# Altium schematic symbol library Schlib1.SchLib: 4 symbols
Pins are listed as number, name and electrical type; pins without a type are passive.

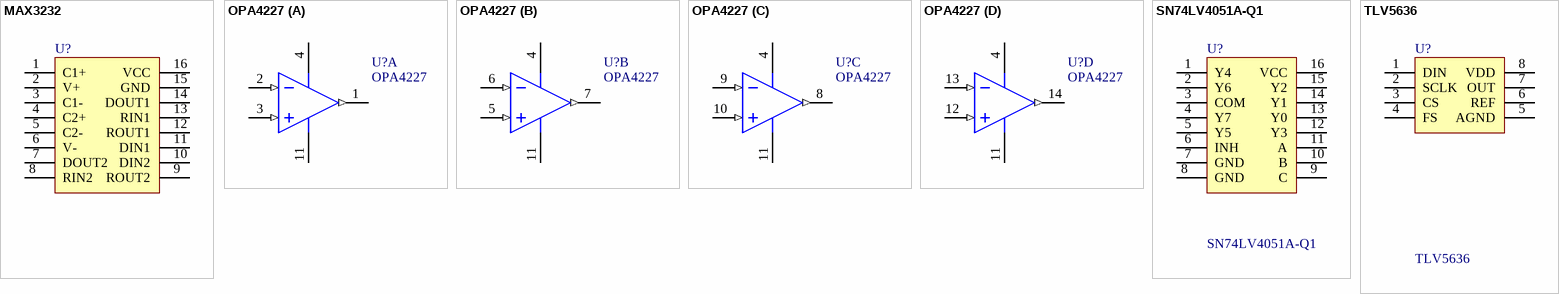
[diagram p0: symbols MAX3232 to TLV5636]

## MAX3232
designator U?
footprint MAX3232
footprint D014_L (SOIC, 14-Leads, Body 8.7x3.9mm, Pitch 1.27mm, IPC High Density)
footprint D014_M (SOIC, 14-Leads, Body 8.7x3.9mm, Pitch 1.27mm, IPC Low Density)
3D model D014 (14-Pin Small Outline Integrated Circuit 1.27 mm Pitch)
pins: 1 C1+, 2 V+, 3 C1-, 4 C2+, 5 C2-, 6 V-, 7 DOUT2, 8  RIN2, 9 ROUT2, 10 DIN2, 11 DIN1, 12 ROUT1, 13 RIN1, 14 DOUT1, 15 GND, 16 VCC

## OPA4227
designator U?
ComponentAvailability: Obsolete
footprint OPA4227
3D model J014 (DIP; 14 Leads; Row Spacing 7.62 mm; Pitch 2.54 mm)
pins on every part: 4 V+ (power), 11 V- (power)
part A pins: 1 OUT (out), 2 IN- (in), 3 IN+ (in)
part B pins: 5 IN+ (in), 6 IN- (in), 7 OUT (out)
part C pins: 8 OUT (out), 9 IN- (in), 10 IN+ (in)
part D pins: 12 IN+ (in), 13 IN- (in), 14 OUT (out)

## SN74LV4051A-Q1
designator U?
footprint SN74LV4051A-Q1
footprint D014_L (SOIC, 14-Leads, Body 8.7x3.9mm, Pitch 1.27mm, IPC High Density)
footprint D014_M (SOIC, 14-Leads, Body 8.7x3.9mm, Pitch 1.27mm, IPC Low Density)
3D model D014 (14-Pin Small Outline Integrated Circuit 1.27 mm Pitch)
pins: 1 Y4, 2 Y6, 3 COM, 4 Y7, 5 Y5, 6 INH, 7 GND, 8  GND, 9 C, 10 B, 11 A, 12 Y3, 13 Y0, 14 Y1, 15 Y2, 16 VCC

## TLV5636
designator U?
footprint TLV5636
footprint FN020_L (Leaded Chip Carrier, 20-Leads, Body 9x9mm, Pitch 1.27mm, IPC High Density)
footprint FN020_M (Leaded Chip Carrier, 20-Leads, Body 9x9mm, Pitch 1.27mm, IPC Low Density)
3D model AD7533-FN020 (20-Pin Leaded Chip Carrier 1.27 mm Pitch)
pins: 1 DIN, 2 SCLK, 3 CS, 4 FS, 5 AGND, 6 REF, 7 OUT, 8 VDD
